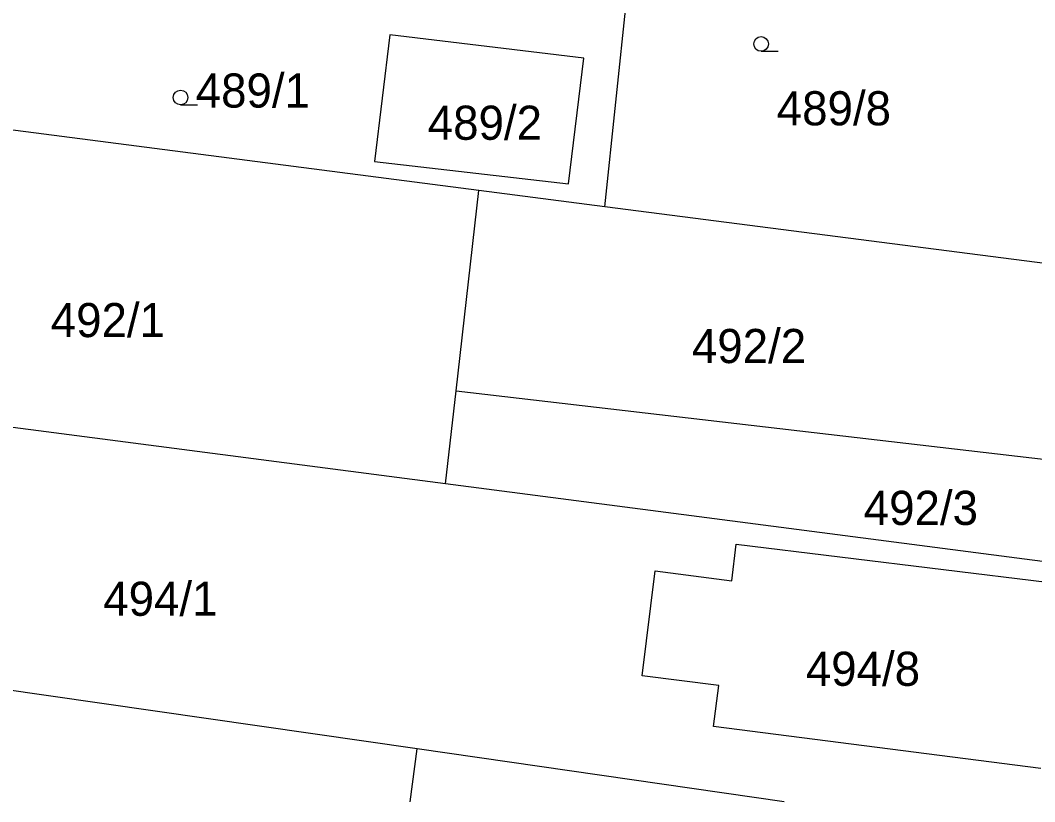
# Model space of a CAD drawing. Extents: x -643342 to -638635, y -1201752 to -1189948.
# Drawn here: x -639444 to -639392, y -1192772.1 to -1192732 of the extents above; entities that cross this region are included whole.
import ezdxf

# ---------------------------------------------------------------- set-up
doc = ezdxf.new("R2010")
doc.units = 0
for name, color, linetype in [('K-HRANICE_KN', 7, 'Continuous'), ('K-ČÍSLA_PARCEL', 7, 'Continuous'), ('Z-značky', 7, 'Continuous')]:
    doc.layers.add(name, color=color, linetype=linetype)

msp = doc.modelspace()

# ---------------------------------------------------------------- linework, layer by layer
at = {"layer": 'K-HRANICE_KN'}
for p, q in [((-639413.99, -1192741.6), (-639412.53, -1192727.63)), ((-639425.02, -1192732.78), (-639425.8, -1192739.27)), ((-639415.08, -1192733.98), (-639425.02, -1192732.78)), ((-639415.86, -1192740.42), (-639415.08, -1192733.98)), ((-639420.45, -1192740.76), (-639446.92, -1192737.34)), ((-639425.8, -1192739.27), (-639415.86, -1192740.42)), ((-639421.62, -1192751.04), (-639420.45, -1192740.76)), ((-639413.99, -1192741.6), (-639420.45, -1192740.76)), ((-639366.85, -1192747.69), (-639413.99, -1192741.6)), ((-639422.16, -1192755.8), (-639457.18, -1192751.25)), ((-639422.16, -1192755.8), (-639421.62, -1192751.04)), ((-639421.62, -1192751.04), (-639391.38, -1192754.55)), ((-639368.63, -1192762.76), (-639422.16, -1192755.8)), ((-639407.49, -1192760.78), (-639407.26, -1192758.89)), ((-639407.26, -1192758.89), (-639391.33, -1192760.84)), ((-639412.08, -1192765.64), (-639411.41, -1192760.27)), ((-639411.41, -1192760.27), (-639407.49, -1192760.78)), ((-639423.61, -1192769.39), (-639465.28, -1192763.39)), ((-639408.16, -1192766.14), (-639412.08, -1192765.64)), ((-639408.42, -1192768.25), (-639408.16, -1192766.14)), ((-639391.65, -1192770.4), (-639408.42, -1192768.25)), ((-639423.982, -1192772.102), (-639423.61, -1192769.39)), ((-639404.804, -1192772.102), (-639423.61, -1192769.39))]:
    msp.add_line(p, q, dxfattribs=at)
at = {"layer": 'Z-značky'}
for p, q in [((-639405.989, -1192733.621), (-639405.114, -1192733.621)), ((-639435.747, -1192736.367), (-639434.872, -1192736.367))]:
    msp.add_line(p, q, dxfattribs=at)
for centre in [(-639405.989, -1192733.246), (-639435.747, -1192735.992)]:
    msp.add_circle(centre, 0.375, dxfattribs=at)

# ---------------------------------------------------------------- texts
at = {"layer": 'K-ČÍSLA_PARCEL'}
for s, p in [('489/1', (-639434.97, -1192736.51)), ('489/8', (-639405.185, -1192737.42)), ('489/2', (-639423.075, -1192738.16)), ('492/1', (-639442.4, -1192748.28)), ('492/2', (-639409.535, -1192749.61)), ('492/3', (-639400.725, -1192757.91)), ('494/1', (-639439.71, -1192762.57)), ('494/8', (-639403.695, -1192766.16))]:
    msp.add_text(s, height=1.75, dxfattribs=at).set_placement(p)

doc.saveas('drawing.dxf')
